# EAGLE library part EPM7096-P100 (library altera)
EPM7096 MAX 7000 family
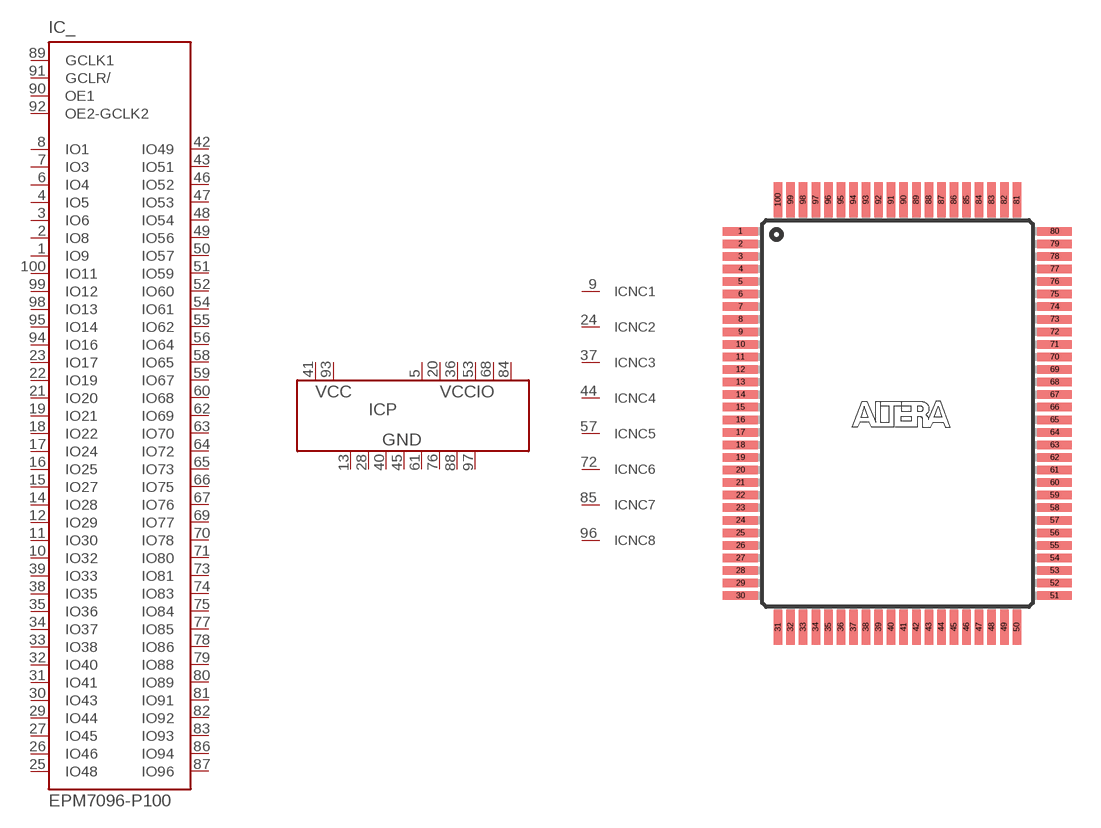
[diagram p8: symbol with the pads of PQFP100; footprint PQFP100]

Designator prefix IC; gates P=PWR8-2-6 NC1=NC NC2=NC NC3=NC NC4=NC NC5=NC NC6=NC NC7=NC NC8=NC _=7096

## EPM7096-P100 (MPN: EPM7096QC100-10; OC_FARNELL: unknown; OC_NEWARK: 51R9665)  [PQFP100]
1  _:IO9
2  _:IO8
3  _:IO6
4  _:IO5
5  P:VCCIO  pwr
6  _:IO4
7  _:IO3
8  _:IO1
9  NC1:NC  nc
10  _:IO32
11  _:IO30
12  _:IO29
13  P:GND  pwr
14  _:IO28
15  _:IO27
16  _:IO25
17  _:IO24
18  _:IO22
19  _:IO21
20  P:VCCIO  pwr
21  _:IO20
22  _:IO19
23  _:IO17
24  NC2:NC  nc
25  _:IO48
26  _:IO46
27  _:IO45
28  P:GND  pwr
29  _:IO44
30  _:IO43
31  _:IO41
32  _:IO40
33  _:IO38
34  _:IO37
35  _:IO36
36  P:VCCIO  pwr
37  NC3:NC  nc
38  _:IO35
39  _:IO33
40  P:GND  pwr
41  P:VCC  pwr
42  _:IO49
43  _:IO51
44  NC4:NC  nc
45  P:GND  pwr
46  _:IO52
47  _:IO53
48  _:IO54
49  _:IO56
50  _:IO57
51  _:IO59
52  _:IO60
53  P:VCCIO  pwr
54  _:IO61
55  _:IO62
56  _:IO64
57  NC5:NC  nc
58  _:IO65
59  _:IO67
60  _:IO68
61  P:GND  pwr
62  _:IO69
63  _:IO70
64  _:IO72
65  _:IO73
66  _:IO75
67  _:IO76
68  P:VCCIO  pwr
69  _:IO77
70  _:IO78
71  _:IO80
72  NC6:NC  nc
73  _:IO81
74  _:IO83
75  _:IO84
76  P:GND  pwr
77  _:IO85
78  _:IO86
79  _:IO88
80  _:IO89
81  _:IO91
82  _:IO92
83  _:IO93
84  P:VCCIO  pwr
85  NC7:NC  nc
86  _:IO94
87  _:IO96
88  P:GND  pwr
89  _:GCLK1  in
90  _:OE1  in
91  _:GCLR/  in
92  _:OE2-GCLK2  in
93  P:VCC  pwr
94  _:IO16
95  _:IO14
96  NC8:NC  nc
97  P:GND  pwr
98  _:IO13
99  _:IO12
100  _:IO11

## Footprint PQFP100 (pad centres in mm)
Plastic Quad Flat Pack
smd 1.8 x 0.44: 1 -8.125,9.425; 2 -8.125,8.775; 3 -8.125,8.125; 4 -8.125,7.475; 5 -8.125,6.825; 6 -8.125,6.175; 7 -8.125,5.525; 8 -8.125,4.875; 9 -8.125,4.225; 10 -8.125,3.575; 11 -8.125,2.925; 12 -8.125,2.275; 13 -8.125,1.625; 14 -8.125,0.975; 15 -8.125,0.325; 16 -8.125,-0.325; 17 -8.125,-0.975; 18 -8.125,-1.625; 19 -8.125,-2.275; 20 -8.125,-2.925; 21 -8.125,-3.575; 22 -8.125,-4.225; 23 -8.125,-4.875; 24 -8.125,-5.525; 25 -8.125,-6.175; 26 -8.125,-6.825; 27 -8.125,-7.475; 28 -8.125,-8.125; 29 -8.125,-8.775; 30 -8.125,-9.425; 51 8.125,-9.425; 52 8.125,-8.775; 53 8.125,-8.125; 54 8.125,-7.475; 55 8.125,-6.825; 56 8.125,-6.175; 57 8.125,-5.525; 58 8.125,-4.875; 59 8.125,-4.225; 60 8.125,-3.575; 61 8.125,-2.925; 62 8.125,-2.275; 63 8.125,-1.625; 64 8.125,-0.975; 65 8.125,-0.325; 66 8.125,0.325; 67 8.125,0.975; 68 8.125,1.625; 69 8.125,2.275; 70 8.125,2.925; 71 8.125,3.575; 72 8.125,4.225; 73 8.125,4.875; 74 8.125,5.525; 75 8.125,6.175; 76 8.125,6.825; 77 8.125,7.475; 78 8.125,8.125; 79 8.125,8.775; 80 8.125,9.425
smd 0.44 x 1.8: 31 -6.175,-11.05; 32 -5.525,-11.05; 33 -4.875,-11.05; 34 -4.225,-11.05; 35 -3.575,-11.05; 36 -2.925,-11.05; 37 -2.275,-11.05; 38 -1.625,-11.05; 39 -0.975,-11.05; 40 -0.325,-11.05; 41 0.325,-11.05; 42 0.975,-11.05; 43 1.625,-11.05; 44 2.275,-11.05; 45 2.925,-11.05; 46 3.575,-11.05; 47 4.225,-11.05; 48 4.875,-11.05; 49 5.525,-11.05; 50 6.175,-11.05; 81 6.175,11.05; 82 5.525,11.05; 83 4.875,11.05; 84 4.225,11.05; 85 3.575,11.05; 86 2.925,11.05; 87 2.275,11.05; 88 1.625,11.05; 89 0.975,11.05; 90 0.325,11.05; 91 -0.325,11.05; 92 -0.975,11.05; 93 -1.625,11.05; 94 -2.275,11.05; 95 -2.925,11.05; 96 -3.575,11.05; 97 -4.225,11.05; 98 -4.875,11.05; 99 -5.525,11.05; 100 -6.175,11.05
